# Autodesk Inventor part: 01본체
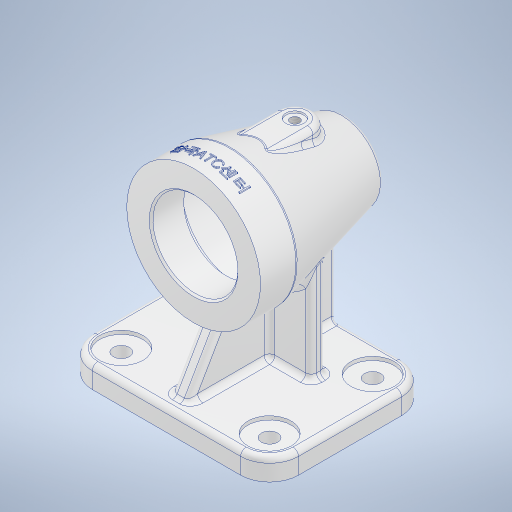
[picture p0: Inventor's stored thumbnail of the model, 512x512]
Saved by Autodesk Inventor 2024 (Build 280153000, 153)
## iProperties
Created: 2024-12
Part Number: 01본체
Material: 알루미늄 6061
Document SubType Name: Modeling
Designer: user
Density: 2.7 g/cm^3
Appearance: 알루미늄 - 평지
Mass: 740.131 g
Surface Area: 668.51 cm^2
Volume: 274.123 cm^3
Author: user
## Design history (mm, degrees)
sketch "스케치2"
  geometry: L1 (0, 56)-(0, -28); L2 (0, -28)-(21, -28); L3 (37, 36)-(37, 56); L4 (37, 56)-(0, 56); L5 (37, 36)-(21, -28); 1 further point
  constraints: 10 end point, 2 perpendicular, 1 horizontal, 1 vertical, 1 vertical alignment
  dimensions: "d5" = 84 distance of L1.start L1.end; "d7" = 20 distance of L3.start L3.end; "d8" = 42 diameter of L2.end L1; "d9" = 74 diameter of L3 L1; "d38" = 56 distance of point (0, 0) L1.start
revolve "회전1" sketch "스케치2" stored, may be unused: angle "d23" = 90 deg
fillet "모깎기1" dims "d24" = 3
node "작업 평면1"
sketch "스케치3"
  geometry: L1 (57, -18)-(-57, -18); L2 (-57, -18)-(-57, 71); L3 (-57, 71)-(57, 71); L4 (57, 71)-(57, -18); L5 (57, -18)-(-57, 71); L6 (-57, -18)-(57, 71); 2 further points
  constraints: 12 end point, 2 midpoint, 2 parallel, 1 horizontal, 1 perpendicular, 1 vertical alignment
  dimensions: "d29" = 71 distance from line of point (0, 0) L3; "d30" = 89 distance of L1.end L2.end; "d31" = 114 distance of L1.start L1.end
extrude "돌출2" join sketch "스케치3" distance "d32" = 12; taper "d33" = 0 deg
fillet "모깎기2" dims "d34" = 16
sketch "스케치4"
  geometry: L1 (41, 18)-(-41, 18) reference; L2 (-28, -11)-(28, -11); L3 (28, -11)-(28, -19); L4 (28, -19)-(-28, -19); L5 (-28, -19)-(-28, -11); L6 (-28, -11)-(28, -19); L7 (28, -11)-(-28, -19); 2 further points
  constraints: 12 end point, 2 midpoint, 2 parallel, 1 horizontal, 1 perpendicular, 1 vertical alignment
  dimensions: "d35" = 8 distance of L2.end L3.end; "d36" = 56 distance of L2.start L2.end; "d37" = 29 distance between parallel lines of L1 L2
extrude "돌출3" join sketch "스케치4" stored distance "d39" = 12; taper "d40" = 0 deg
sketch "스케치5"
  geometry: L1 (36.91, 35.642)-(21.568, -25.728) reference; L2 (18.658, -28)-(-18.658, -28) reference; L3 (-21.568, -25.728)-(-30.75, 11) reference; L4 (-30.75, 11)-(-70, 11) reference; L5 (-70, 11)-(-70, -18) reference; L6 (-70, -18)-(-82, -18) reference; L7 (-82, -18)-(-82, 71) reference; L8 (-82, 71)-(-70, 71) reference; L9 (-70, 71)-(-70, 19) reference; L10 (-70, 19)-(-32.75, 19) reference; L11 (-32.75, 19)-(-36.91, 35.642) reference; L12 (-37, 36.369)-(-37, 56) reference; L13 (-37, 56)-(37, 56) reference; L14 (37, 56)-(37, 36.369) reference; L15 (-70, 64)-(0, 23.585); L16 (0, 23.585)-(0, -18); L17 (36.91, 35.642)-(-36.91, 35.642) reference; L18 (0, -18)-(-70, -18); L19 (-70, 64)-(-70, -18); A1 r 3 centre (18.658, -25) between (18.658, -28) and (21.568, -25.728) reference; A2 r 3 centre (-18.658, -25) between (-21.568, -25.728) and (-18.658, -28) reference; A3 r 3 centre (-34, 36.369) between (-37, 36.369) and (-36.91, 35.642) reference; A4 r 3 centre (34, 36.369) between (36.91, 35.642) and (37, 36.369) reference; 1 further point
  constraints: 8 end point, 2 point on line, 1 collinear, 1 horizontal, 1 perpendicular
  dimensions: "d41" = 60 deg angle of L9 L15; "d42" = 7 distance of L15.start L8.end
extrude "돌출4" join sketch "스케치5" stored distance "d43" = 10; taper "d44" = 0 deg
node "작업 평면2"
sketch "스케치7"
  geometry: L1 (-10, 25.928)-(10, 25.928); L2 (10, 25.928)-(10, 0); L3 (10, 0)-(-10, 0); L4 (-10, 0)-(-10, 25.928); L5 (-16.733, 36.369)-(-16.733, 56) reference; L6 (-16.733, 56)-(16.733, 56) reference; L7 (16.733, 56)-(16.733, 36.369) reference; A1 r 10 centre (0, 0) between (-10, 0) and (10, 0); A2 r 10 centre (0, 0) between (10, 0) and (-10, 0); 3 further points
  constraints: 8 end point, 4 point on circle, 2 centre point, 2 parallel, 1 coincident, 1 horizontal, 1 midpoint, 1 perpendicular, 4 other
  dimensions: "d61" = 20 distance of L1.start L1.end
extrude "돌출5" join sketch "스케치7" distance "d63" = 8.509; taper "d64" = 0 deg
sketch "스케치6"
  geometry: L1 (-21.568, -25.728)-(-23.5, -18) reference; L2 (-23.5, -18)-(-82, -18) reference; L3 (-82, -18)-(-82, 71) reference; L4 (-82, 71)-(-70, 71) reference; L5 (-70, 71)-(-70, 64) reference; L6 (-70, 64)-(-37, 44.947) reference; L7 (-37, 44.947)-(-37, 56) reference; L8 (-37, 56)-(37, 56) reference; L9 (37, 56)-(37, 36.369) reference; L10 (36.91, 35.642)-(33, 20) reference; L11 (18.658, -28)-(-18.658, -28) reference; L12 (23.5, 56)-(23.5, 38); L13 (23.5, 38)-(25.942, 38); L14 (30.793, 31.787)-(21.664, -4.728); L15 (18.754, -7)-(17.5, -7); L16 (17.5, -7)-(17.5, -16.7); L17 (17.2, -17)-(15.5, -17); L18 (15.5, -17)-(15.5, -17); L19 (12.5, -20)-(0, -20); L20 (0, 56)-(0, -28); L21 (23.5, 56)-(0, 56); L22 (-37, 56)-(37, 56) reference; L23 (33, 20)-(33, -10) reference; L24 (33, -10)-(25.5, -10) reference; L25 (25.5, -10)-(21.568, -25.728) reference; A1 r 3 centre (34, 36.369) between (36.91, 35.642) and (37, 36.369) reference; A2 r 3 centre (18.658, -25) between (18.658, -28) and (21.568, -25.728) reference; A3 r 3 centre (-18.658, -25) between (-21.568, -25.728) and (-18.658, -28) reference; A4 r 5 centre (25.942, 33) between (30.793, 31.787) and (25.942, 38); A5 r 3 centre (18.754, -4) between (18.754, -7) and (21.664, -4.728); A6 r 3 centre (12.5, -17) between (12.5, -20) and (15.5, -17); A7 r 0.3 centre (17.2, -16.7) between (17.2, -17) and (17.5, -16.7); 7 further points
  constraints: 20 end point, 10 point on line, 8 point on circle, 8 tangent, 4 centre point, 3 midpoint, 3 perpendicular, 2 horizontal, 2 vertical, 1 collinear, 1 equal radius, 1 parallel
  dimensions: "d45" = 18 distance of L12.start L12.end; "d46" = 45 vertical distance of point (21.096, -7) point (32.346, 38); "d47" = 10 distance of L15.end point (17.5, -17); "d48" = 3 distance of L17.end point (15.5, -20); "d49" = 47 diameter of L12 L20; "d50" = 5 distance between parallel lines of L10 L14; "d51" = 35 diameter of L16 L20; "d52" = 31 diameter of point (15.5, -17) L20; "d53" = 5 radius of A4; "d54" = 3 radius of A5; "d55" = 0.3 radius of A7
revolve "회전2" sketch "스케치6" stored, may be unused: angle "d56" = 90 deg
chamfer "모따기2" distance "d57" = 1; stored, may be unused: second distance "d58" = 2, angle "d59" = 45 deg
sketch "스케치8"
  geometry: C1 r 5 at (0, 0); A1 r 10 centre (0, 0) between (10, 0) and (-10, 0) reference
  constraints: 1 centre point, 1 coincident
  dimensions: "d65" = 10 diameter of C1
extrude "돌출6" cut sketch "스케치8" distance "d66" = 1; taper "d67" = 0 deg
sketch "스케치9"
  geometry: C1 r 5 at (0, 0) reference
hole "구멍1" sketch "스케치9" at (0, 0) diameter "d68" = 5.1881; stored, may be unused: countersink angle "d72" = 90 deg, drill point angle "d74" = 118 deg; dims "d69" = 12, "d70" = 4, "d71" = 2, "d73" = 10.75
fillet "모깎기3" dims "d75" = 3
fillet "모깎기4" dims "d76" = 3
sketch "스케치11"
  geometry: A1 r 13 centre (-41, 2) between (-41, 15) and (-54, 2) reference; A2 r 13 centre (-41, -55) between (-54, -55) and (-41, -68) reference; A3 r 13 centre (41, -55) between (41, -68) and (54, -55) reference; A4 r 13 centre (41, 2) between (54, 2) and (41, 15) reference; 1 further point
hole "구멍2" sketch "스케치11" at (41, -55), (41, 2), (-41, 2), (-41, -55) diameter "d77" = 9; stored, may be unused: countersink angle "d81" = 90 deg, drill point angle "d83" = 118 deg; dims "d78" = 12, "d79" = 24, "d80" = 2, "d82" = 10.75
node "작업 평면3"
sketch "스케치12"
  geometry: L1 (37, -56)-(-37, -56) reference; 2 further points
  constraints: 1 vertical alignment, 1 other
  dimensions: "d85" = 9 distance from line of L1 point (0, -47)
feature "엠보싱1" sketch "스케치12" dims "d5" = 84, "d7" = 20, "d8" = 42, "d9" = 74, "d38" = 56, "d86" = 0.5, "d87" = 0
node "솔리드2"
node "절단 모서리 투영1"
node "절단 모서리 투영2"
node "절단 모서리 투영3"
feature "A9D066F2-1C7D-4E18-AEED-F7BC21143FA4" dims "d77" = 9, "d78" = 12, "d79" = 24, "d80" = 2, "d81" = 90 deg, "d82" = 10.75, "d83" = 118 deg
other parameters: "d28" = -82, "d60" = -115, "d84" = 115.5
